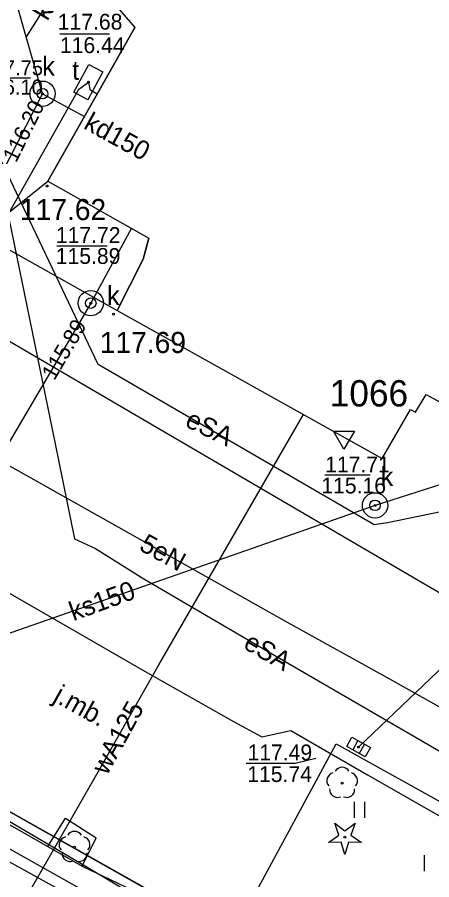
# Model space of a CAD drawing. Extents: x 6434771 to 6436222, y 5663454 to 5664782.
# Drawn here: x 6435336.31 to 6435355.97, y 5663856.09 to 5663897 of the extents above; entities that cross this region are included whole.
import ezdxf

# ---------------------------------------------------------------- set-up
doc = ezdxf.new("R2010")
doc.units = 0
for name, color, linetype in [('Warstwa 1', 7, 'Continuous'), ('Warstwa 10', 7, 'Continuous'), ('Warstwa 11', 7, 'Continuous'), ('Warstwa 12', 7, 'Continuous'), ('Warstwa 13', 7, 'Continuous'), ('Warstwa 14', 7, 'Continuous'), ('Warstwa 15', 7, 'Continuous'), ('Warstwa 25', 7, 'Continuous'), ('Warstwa 4', 7, 'Continuous'), ('Warstwa 5', 7, 'Continuous'), ('Warstwa 6', 7, 'Continuous'), ('Warstwa 7', 7, 'Continuous'), ('Warstwa 8', 7, 'Continuous'), ('Warstwa 9', 7, 'Continuous')]:
    doc.layers.add(name, color=color, linetype=linetype)

msp = doc.modelspace()

# ---------------------------------------------------------------- linework, layer by layer
at = {"layer": 'Warstwa 1'}
msp.add_line((6435319.457, 5663868.606), (6435372.859, 5663838.53), dxfattribs=at)
msp.add_line((6435319.457, 5663868.606), (6435372.859, 5663838.53), dxfattribs=at)
msp.add_lwpolyline([(6435339.036, 5663899.822), (6435341.886, 5663896.517), (6435337.768, 5663889.226), (6435342.556, 5663886.519), (6435342.284, 5663885.522), (6435341.054, 5663883.097), (6435353.621, 5663876.074), (6435354.969, 5663878.388), (6435355.207, 5663878.275), (6435355.708, 5663879.109), (6435360.526, 5663876.441)], dxfattribs=at)
at = {"layer": 'Warstwa 10'}
for points in [[(6435283.121, 5663900.196), (6435296.714, 5663892.598), (6435309.613, 5663885.333), (6435320.245, 5663879.276), (6435332.639, 5663872.311), (6435332.336, 5663871.75), (6435334.444, 5663870.542), (6435342.379, 5663865.968), (6435346.568, 5663863.606), (6435347.919, 5663862.872), (6435349.292, 5663863.177), (6435352.92, 5663861.064), (6435362.538, 5663855.579)], [(6435401.146, 5663821.695), (6435398.047, 5663823.455), (6435390.791, 5663827.598), (6435381.56, 5663832.922), (6435372.833, 5663837.811), (6435368.692, 5663840.176), (6435362.365, 5663843.722), (6435347.821, 5663851.905), (6435346.344, 5663852.663), (6435339.267, 5663856.894), (6435330.773, 5663861.869), (6435330.105, 5663862.165), (6435320.767, 5663867.824), (6435312.71, 5663872.596), (6435305.938, 5663876.652), (6435298.004, 5663881.189), (6435285.783, 5663888.133), (6435276.948, 5663893.06)], [(6435359.022, 5663874.085), (6435353.868, 5663873.017), (6435353.242, 5663872.929), (6435340.153, 5663880.527), (6435335.178, 5663890.938)], [(6435335.178, 5663890.938), (6435338.107, 5663876.762), (6435339.024, 5663872.265), (6435340.015, 5663871.796), (6435342.311, 5663870.369), (6435348.64, 5663866.658), (6435357.869, 5663861.307), (6435368.081, 5663855.303), (6435372.357, 5663852.748), (6435378.044, 5663849.395), (6435386.974, 5663844.189), (6435394.104, 5663839.85), (6435398.635, 5663837.219), (6435400.345, 5663836.282), (6435405.663, 5663833.365), (6435414.229, 5663828.613), (6435413.94, 5663822.627), (6435413.836, 5663820.771), (6435413.916, 5663820.663), (6435415.865, 5663819.454), (6435420.004, 5663817.009), (6435420.232, 5663816.158), (6435417.642, 5663813.363)]]:
    msp.add_lwpolyline(points, dxfattribs=at)
msp.add_lwpolyline([(6435351.069, 5663857.86), (6435351.571, 5663858.207), (6435351.369, 5663858.783), (6435351.854, 5663858.413), (6435352.339, 5663858.783), (6435352.137, 5663858.207), (6435352.639, 5663857.86), (6435352.029, 5663857.874), (6435351.854, 5663857.29), (6435351.679, 5663857.874)], close=True, dxfattribs=at)
msp.add_circle((6435351.854, 5663858.115), 0.05, dxfattribs=at)
at = {"layer": 'Warstwa 11'}
for centre in [(6435351.724, 5663860.677), (6435339.028, 5663857.639)]:
    msp.add_circle(centre, 0.05, dxfattribs=at)
for centre, start, end in [((6435351.367, 5663860.793), 102.1471, 221.8529), ((6435351.724, 5663861.052), 30.1471, 149.8529), ((6435352.081, 5663860.793), 318.1471, 77.8529), ((6435351.504, 5663860.374), 174.1471, 293.8529), ((6435351.944, 5663860.374), 246.1471, 5.8529), ((6435339.028, 5663858.014), 30.1471, 149.8529), ((6435338.671, 5663857.755), 102.1471, 221.8529), ((6435339.385, 5663857.755), 318.1471, 77.8529), ((6435338.808, 5663857.336), 174.1471, 293.8529), ((6435339.248, 5663857.336), 246.1471, 5.8529)]:
    msp.add_arc(centre, 0.375, start, end, dxfattribs=at)
at = {"layer": 'Warstwa 12'}
for points in [[(6435463.66, 5663935.12), (6435460.91, 5663924.89), (6435462.44, 5663921.82), (6435441.07, 5663889.25), (6435356.73, 5663869.46), (6435331.52, 5663884.2), (6435330.44, 5663887.89), (6435327.58, 5663889.55), (6435318.31, 5663921.18), (6435313.59, 5663921.38), (6435311.91, 5663927.16), (6435315.9, 5663929.81), (6435312.06, 5663943.65)], [(6435331.218, 5663879.313), (6435331.423, 5663879.773), (6435339.231, 5663893.589), (6435339.685, 5663893.924), (6435339.751, 5663893.563), (6435340.102, 5663893.358)], [(6435288.007, 5663877.155), (6435288.46, 5663877.667), (6435290.15, 5663880.879), (6435294.824, 5663890.045), (6435319.611, 5663875.535), (6435328.457, 5663881.789), (6435337.768, 5663889.226)], [(6435371.655, 5663864.561), (6435369.375, 5663860.341), (6435367.872, 5663857.764), (6435364.724, 5663859.577), (6435353.986, 5663865.613), (6435349.138, 5663868.297), (6435343.27, 5663871.593), (6435332.691, 5663877.545), (6435324.085, 5663882.425), (6435323.793, 5663882.644), (6435323.959, 5663883.045), (6435326.561, 5663887.234), (6435328.01, 5663889.543)], [(6435416.166, 5663827.977), (6435399.481, 5663837.679), (6435393.426, 5663827.371), (6435391.836, 5663824.89), (6435366.814, 5663839.843), (6435332.256, 5663858.96), (6435321.402, 5663864.883), (6435291.11, 5663881.519), (6435276.903, 5663889.322)], [(6435335.305, 5663852.832), (6435335.928, 5663853.819), (6435337.094, 5663855.885), (6435340.084, 5663861.097), (6435343.032, 5663866.287), (6435349.894, 5663878.157)], [(6435320.062, 5663866.479), (6435323.903, 5663864.281), (6435335.194, 5663857.963), (6435342.155, 5663854.067), (6435347.738, 5663850.877), (6435354.444, 5663847.135), (6435364.02, 5663841.7), (6435368.911, 5663838.95), (6435371.302, 5663837.61)]]:
    msp.add_lwpolyline(points, dxfattribs=at)
at = {"layer": 'Warstwa 14'}
for p, q in [((6435338.33, 5663896.214), (6435340.685, 5663896.214)), ((6435334.715, 5663894.13), (6435336.946, 5663894.13)), ((6435338.188, 5663886.156), (6435340.573, 5663886.156)), ((6435350.906, 5663875.289), (6435353.054, 5663875.289))]:
    msp.add_line(p, q, dxfattribs=at)
msp.add_lwpolyline([(6435347.178, 5663861.617), (6435349.497, 5663861.617), (6435350.474, 5663861.861)], dxfattribs=at)
for centre in [(6435339.685, 5663893.924), (6435337.508, 5663893.37), (6435337.508, 5663893.37), (6435339.798, 5663883.442), (6435339.798, 5663883.442), (6435353.284, 5663873.848), (6435352.505, 5663862.387)]:
    msp.add_circle(centre, 0.045, dxfattribs=at)
at = {"layer": 'Warstwa 15'}
for centre in [(6435337.508, 5663893.37), (6435339.798, 5663883.442), (6435353.284, 5663873.848)]:
    msp.add_circle(centre, 0.6, dxfattribs=at)
at = {"layer": 'Warstwa 25'}
for centre in [(6435337.729, 5663888.994), (6435340.878, 5663882.918)]:
    msp.add_circle(centre, 0.045, dxfattribs=at)
at = {"layer": 'Warstwa 4'}
for p, q in [((6435352.473, 5663862.69), (6435352.231, 5663862.253)), ((6435352.779, 5663862.521), (6435352.537, 5663862.084))]:
    msp.add_line(p, q, dxfattribs=at)
for points in [[(6435339.657, 5663893.086), (6435338.998, 5663893.444), (6435339.713, 5663894.762), (6435340.372, 5663894.404)], [(6435352.188, 5663862.848), (6435353.064, 5663862.364), (6435352.822, 5663861.926), (6435351.946, 5663862.41)]]:
    msp.add_lwpolyline(points, close=True, dxfattribs=at)
for centre in [(6435337.508, 5663893.37), (6435339.798, 5663883.442), (6435353.284, 5663873.848)]:
    msp.add_circle(centre, 0.25, dxfattribs=at)
at = {"layer": 'Warstwa 5'}
for p, q in [((6435346.486, 5663853.379), (6435351.447, 5663862.54)), ((6435351.447, 5663862.54), (6435356.354, 5663859.8)), ((6435352.303, 5663859.035), (6435352.303, 5663859.785)), ((6435352.803, 5663859.035), (6435352.803, 5663859.785)), ((6435355.635, 5663856.507), (6435355.635, 5663857.257))]:
    msp.add_line(p, q, dxfattribs=at)
at = {"layer": 'Warstwa 6'}
for points in [[(6435273.017, 5663901.219), (6435305.06, 5663883.021), (6435302.472, 5663878.272), (6435315.434, 5663870.865), (6435319.457, 5663868.606), (6435372.859, 5663838.53), (6435375.407, 5663843.29), (6435404.937, 5663826.552), (6435405.672, 5663826.093), (6435404.72, 5663824.305), (6435401.922, 5663819.558), (6435406.79, 5663816.849), (6435407.946, 5663818.936), (6435411.291, 5663816.875), (6435416.019, 5663814.198), (6435421.61, 5663811.04), (6435514.97, 5663977.09)], [(6435372.859, 5663838.53), (6435319.457, 5663868.606), (6435315.434, 5663870.865), (6435302.472, 5663878.272), (6435305.06, 5663883.021), (6435273.017, 5663901.219)]]:
    msp.add_lwpolyline(points, dxfattribs=at)
for centre in [(6435339.685, 5663893.924), (6435337.508, 5663893.37), (6435339.798, 5663883.442), (6435353.284, 5663873.848), (6435352.505, 5663862.387)]:
    msp.add_circle(centre, 0.045, dxfattribs=at)
at = {"layer": 'Warstwa 7'}
for points in [[(6435328.593, 5663875.627), (6435331.362, 5663881.343), (6435337.508, 5663893.37), (6435336.735, 5663896.07), (6435333.833, 5663906.207), (6435331.332, 5663914.94), (6435329.182, 5663922.449), (6435327.96, 5663926.717), (6435326.648, 5663931.455), (6435323.888, 5663941.424), (6435323.309, 5663943.514)], [(6435434.351, 5663901.79), (6435432.948, 5663899.298), (6435432.031, 5663897.899), (6435402.197, 5663889.439), (6435390.137, 5663885.82), (6435384.227, 5663883.964), (6435377.421, 5663881.796), (6435376.841, 5663881.598), (6435371.458, 5663879.765), (6435364.761, 5663877.53), (6435360.003, 5663875.987), (6435353.284, 5663873.848), (6435329.201, 5663865.434)], [(6435339.069, 5663899.784), (6435336.735, 5663896.07)], [(6435337.508, 5663893.37), (6435339.494, 5663892.282)], [(6435341.725, 5663886.989), (6435339.798, 5663883.442), (6435329.201, 5663865.434)], [(6435352.505, 5663862.387), (6435357.618, 5663867.265)]]:
    msp.add_lwpolyline(points, dxfattribs=at)
at = {"layer": 'Warstwa 8'}
for p, q in [((6435328.985, 5663889.842), (6435341.054, 5663883.097)), ((6435341.054, 5663883.097), (6435353.621, 5663876.074)), ((6435355.207, 5663878.275), (6435355.708, 5663879.109)), ((6435355.708, 5663879.109), (6435360.526, 5663876.441)), ((6435353.621, 5663876.074), (6435354.969, 5663878.388)), ((6435354.969, 5663878.388), (6435355.207, 5663878.275)), ((6435346.486, 5663853.379), (6435351.447, 5663862.54)), ((6435351.447, 5663862.54), (6435356.354, 5663859.8)), ((6435333.883, 5663859.872), (6435337.757, 5663857.665)), ((6435337.757, 5663857.665), (6435338.593, 5663859.015)), ((6435338.593, 5663859.015), (6435340.052, 5663858.077)), ((6435339.396, 5663856.735), (6435340.052, 5663858.077)), ((6435339.396, 5663856.735), (6435346.486, 5663853.379))]:
    msp.add_line(p, q, dxfattribs=at)
at = {"layer": 'Warstwa 9'}
for p, q in [((6435339.036, 5663899.822), (6435341.886, 5663896.517)), ((6435337.768, 5663889.226), (6435341.886, 5663896.517)), ((6435328.985, 5663889.842), (6435341.054, 5663883.097)), ((6435337.768, 5663889.226), (6435342.556, 5663886.519)), ((6435342.284, 5663885.522), (6435342.556, 5663886.519)), ((6435341.054, 5663883.097), (6435342.284, 5663885.522)), ((6435333.883, 5663859.872), (6435337.757, 5663857.665)), ((6435337.757, 5663857.665), (6435339.396, 5663856.735)), ((6435339.396, 5663856.735), (6435346.486, 5663853.379))]:
    msp.add_line(p, q, dxfattribs=at)
msp.add_lwpolyline([(6435351.31, 5663877.375), (6435352.31, 5663877.375), (6435351.81, 5663876.509)], close=True, dxfattribs=at)

# ---------------------------------------------------------------- texts
at = {"layer": 'Warstwa 10'}
msp.add_text('1066', height=1.25, dxfattribs=at).set_placement((6435351.135, 5663878.538))
at = {"layer": 'Warstwa 11'}
for rotation, p in [(334.1146, (6435344.218, 5663877.62)), (330.3102, (6435346.982, 5663867.097))]:
    msp.add_text('eSA', height=0.9, rotation=rotation, dxfattribs=at).set_placement(p)
at = {"layer": 'Warstwa 13'}
for s, rotation, p in [('5eN', 331.3243, (6435342.043, 5663871.754)), ('wA125', 61.0945, (6435340.573, 5663861.014))]:
    msp.add_text(s, height=0.9, rotation=rotation, dxfattribs=at).set_placement(p)
at = {"layer": 'Warstwa 14'}
for s, height, p in [('116.44', 0.75, (6435338.335, 5663895.297)), ('116.10', 0.712, (6435334.61, 5663893.331)), ('115.89', 0.75, (6435338.138, 5663885.299)), ('115.16', 0.75, (6435350.736, 5663874.414)), ('115.74', 0.75, (6435347.223, 5663860.73))]:
    msp.add_text(s, height=height, dxfattribs=at).set_placement(p)
for s, rotation, p in [('116.20', 63.627, (6435336.258, 5663890.067)), ('115.89', 59.5246, (6435338.072, 5663879.738))]:
    msp.add_text(s, height=0.75, rotation=rotation, dxfattribs=at).set_placement(p)
at = {"layer": 'Warstwa 25'}
for s, p in [('117.62', (6435336.438, 5663887.376)), ('117.69', (6435340.226, 5663881.073))]:
    msp.add_text(s, height=1, dxfattribs=at).set_placement(p)
at = {"layer": 'Warstwa 5'}
for s, p in [('k', (6435337.493, 5663894.225)), ('t', (6435338.915, 5663894.031)), ('k', (6435340.564, 5663883.349)), ('k', (6435353.551, 5663874.762))]:
    msp.add_text(s, height=0.9, dxfattribs=at).set_placement(p)
at = {"layer": 'Warstwa 6'}
for s, height, p in [('117.68', 0.75, (6435338.232, 5663896.41)), ('117.75', 0.712, (6435334.62, 5663894.245)), ('117.72', 0.75, (6435338.142, 5663886.295)), ('117.71', 0.75, (6435350.917, 5663875.414)), ('117.49', 0.75, (6435347.235, 5663861.758))]:
    msp.add_text(s, height=height, dxfattribs=at).set_placement(p)
at = {"layer": 'Warstwa 7'}
for s, rotation, p in [('kd150', 58.5448, (6435337.735, 5663896.786)), ('kd150', 331.1983, (6435339.407, 5663891.743)), ('ks150', 19.9561, (6435338.973, 5663868.355))]:
    msp.add_text(s, height=0.9, rotation=rotation, dxfattribs=at).set_placement(p)
at = {"layer": 'Warstwa 8'}
msp.add_text('j.mb.', height=0.9, rotation=330.7342, dxfattribs=at).set_placement((6435337.962, 5663864.593))

doc.saveas('drawing.dxf')
